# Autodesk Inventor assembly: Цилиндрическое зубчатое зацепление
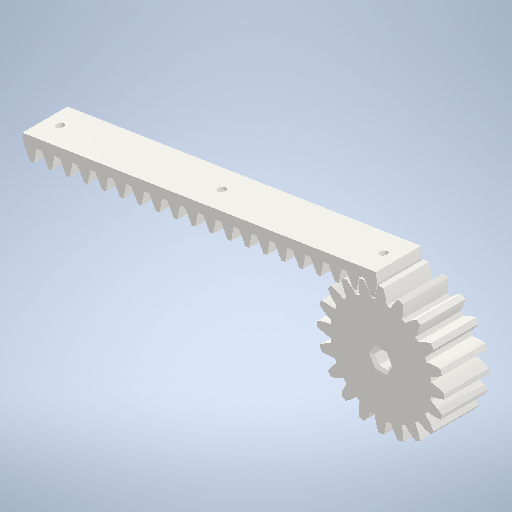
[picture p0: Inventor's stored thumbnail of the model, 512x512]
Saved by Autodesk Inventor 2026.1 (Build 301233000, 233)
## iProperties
ClientObjectVersion: 1
Created: 2026-01
Part Number: Цилиндрическое зубчатое зацепление
Document SubType Name: Assembly
Designer: Yury Melnikov
Categories: <?xml version="1.0" encoding="UTF-16"?> <MemberInstance><Categories><FamilyTemplate/><ParamToTemplateMap><ParamToTemplate><ParamToTemplate CategoryParameter="//
Author: Yury Melnikov
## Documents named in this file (2)
- C:\Users\user\Documents\Проекты\ВсОШ_РОБО\Робот\Сборка1\Мастер проектирования\Цилиндрическое зубчатое зацепление3.iam
- C:\Users\user\Documents\Проекты\ВсОШ_РОБО\Робот\Сборка1\Мастер проектирования\Цилиндрическое зубчатое зацепление13.ipt
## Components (1 placed, 1 different names)
1. Цилиндрическое зубчатое зацепление1:1
